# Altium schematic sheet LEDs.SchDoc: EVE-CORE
size A4; Organization: Ingenia Motion Control; Address1: Carrer Avila, 124, 2B; Address2: 08018 Barcelona Spain; Address3: www.ingeniamc.com; Address4: www.ingeniamc.com; Documentation: https://doc.ingeniamc.com/x/coAZBg
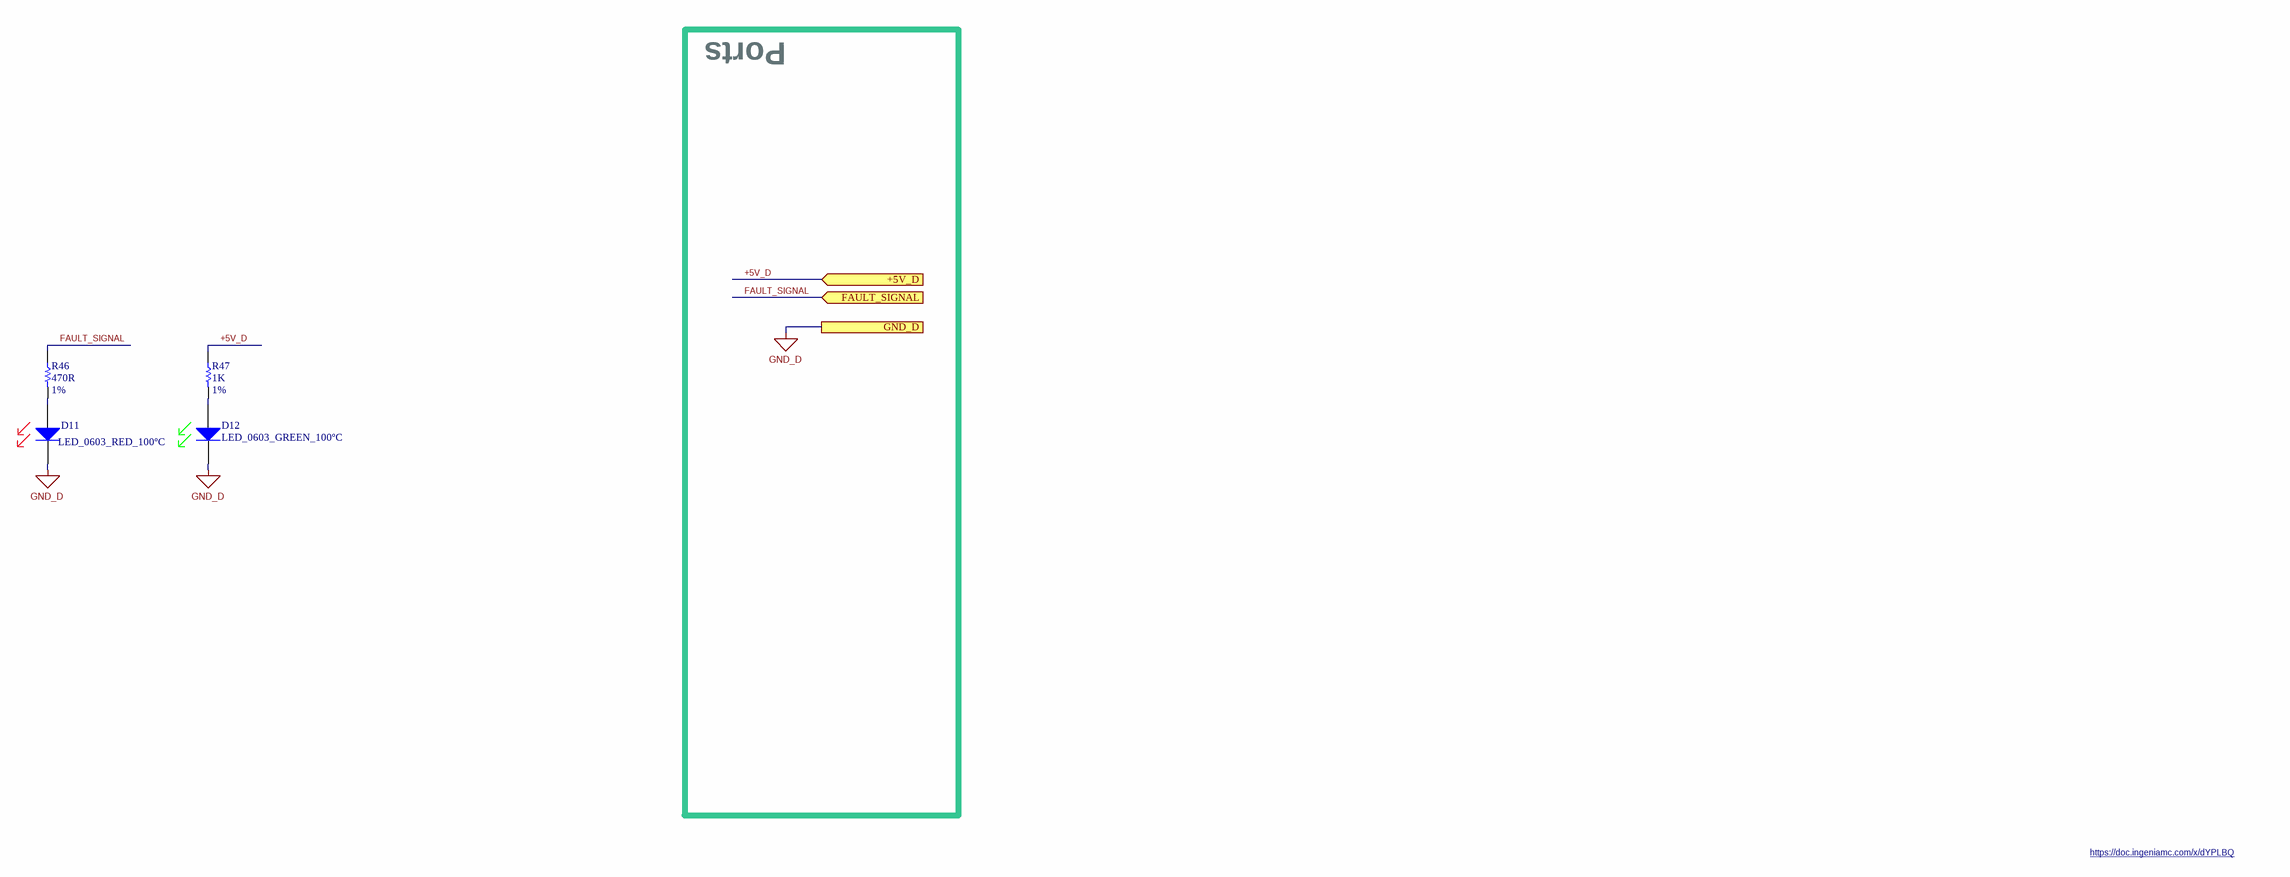
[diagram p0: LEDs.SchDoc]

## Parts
D11  LED_0603_RED_100ºC  [LED_0603]
D12  LED_0603_GREEN_100ºC  [LED_0603]
R46  value 470R  Tolerance: 1%  [R_0402]  (hidden comment: R_0402--470R--1%)
R47  value 1K  Tolerance: 1%  [R_0402]  (hidden comment: R_0402--1K--1%)

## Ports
+5V_D (in), FAULT_SIGNAL (in), GND_D

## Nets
GND_D: D11.2(K) D12.2(K) ; port GND_D
+5V_D: R47.1 ; port +5V_D
FAULT_SIGNAL: R46.1 ; port FAULT_SIGNAL
NetD11_1: D11.1(A) R46.2
NetD12_1: D12.1(A) R47.2

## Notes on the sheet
- Ports
- https://doc.ingeniamc.com/x/dYPLBQ

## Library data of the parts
D11 = LED_0603_RED_100ºC: RED LED, 0603, 100ºC; ManufacturerName: Vishay; ManufacturerPN: TLMS1100-GS08; IsPreferred: 1; IsGeneric: 0; IngeniaID: 1518; TemperatureMaxC: 100; TemperatureMinC: -40
D12 = LED_0603_GREEN_100ºC: GREEN LED, 0603, 100ºC; ManufacturerName: Vishay; ManufacturerPN: TLMG1100-GS08; IsPreferred: 1; IsGeneric: 0; IngeniaID: 1516; TemperatureMaxC: 100; TemperatureMinC: -40
R46 = R_0402[[/\]]470R[[/\]]1%: RES 470 OHM 1/16W 1% 0402 SMD; ManufacturerName: Yageo; ManufacturerPN: RC0402FR-07470RL; AlternativeManufacturer: Panasonic; IsPreferred: 0; IsGeneric: 1; IngeniaID: 692; AlternativePN: ERJ-2RKF4700X
R47 = R_0402[[/\]]1K[[/\]]1%: RES 1K OHM 1/16W 1% 0402 SMD; ManufacturerName: Panasonic Electronic Components; ManufacturerPN: ERJ-2RKF1001X; AlternativeManufacturer: Bourns; IsPreferred: 0; IsGeneric: 1; IngeniaID: 686; TemperatureMaxC: 155; TemperatureMinC: -55; MTBF55h: 91649788; AlternativePN: CR0402-FX-1001GLF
